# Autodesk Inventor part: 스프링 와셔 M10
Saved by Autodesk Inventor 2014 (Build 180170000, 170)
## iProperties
Created: 2026-06
Part Number: 스프링 와셔 M10
Material: 강철, 합금
Document SubType Name: Modeling
Designer: dg
Density: 7.85 g/cm^3
Appearance: 반연마
Mass: 3.09795 g
Surface Area: 5.48825 cm^2
Volume: 0.394643 cm^3
Author: jhkim
Description: 스프링 잠금 와셔
Creation Date: 2026-05-29
Sending System: Autodesk Inventor 2027
Preprocessor: ST-DEVELOPER v20.1
Author: dg
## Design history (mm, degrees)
node "스프링 와셔 M101"
body "Solid1"
node "기준1"
